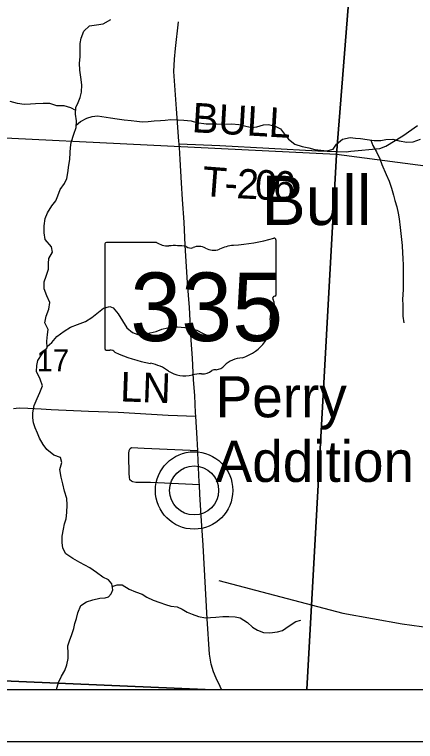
# Model space of a CAD drawing. Extents: x 0 to 40.8, y 0 to 22.
# Drawn here: x 3.599 to 4.37, y 14 to 15.397 of the extents above; entities that cross this region are included whole.
import ezdxf

# ---------------------------------------------------------------- set-up
doc = ezdxf.new("R2010")
doc.units = 0
for name, color, linetype in [('Default', 7, 'Continuous'), ('GM_X_County_Road', 7, 'Continuous'), ('GM_X_Minor_River', 7, 'Continuous'), ('GM_X_Minor_River_Text', 7, 'Continuous'), ('GM_X_Section', 7, 'Continuous'), ('GM_X_Section_Text', 7, 'Continuous'), ('GM_X_State_Location', 7, 'Continuous'), ('GM_X_State_Route', 7, 'Continuous'), ('GM_X_State_Shield', 7, 'Continuous'), ('GM_X_Township_Road', 7, 'Continuous'), ('GM_X_Township_Road_Text', 7, 'Continuous'), ('GM_X_Unincorporated', 7, 'Continuous'), ('GM_X_Unincorporated_Location', 7, 'Continuous'), ('GM_X_Unincorporated_Text', 7, 'Continuous'), ('SH_Cut_Line', 7, 'Continuous'), ('SH_Data', 7, 'Continuous')]:
    doc.layers.add(name, color=color, linetype=linetype)

msp = doc.modelspace()

# ---------------------------------------------------------------- linework, layer by layer
at = {"layer": 'Default'}
msp.add_lwpolyline([(2.1, 16.4387), (2.1, 14.1), (8.9, 14.1), (8.9, 16.9831), (7.7161, 17.0658), (7.7144, 17.066), (7.54, 17.0745), (7.4495, 17.0841), (6.9172, 17.1197), (6.1785, 17.166), (5.6278, 17.197), (5.3407, 17.2146), (4.8294, 17.2493), (4.5348, 17.2687), (3.4481, 17.3334), (3.1244, 17.3534), (2.8484, 17.3691), (2.8463, 17.3693), (2.4594, 17.3966), (2.4379, 17.0913), (2.3911, 16.4258)], close=True, dxfattribs=at)
at = {"layer": 'GM_X_County_Road'}
for points in [[(3.9661, 14.1), (4.1612, 14.1), (4.2184, 15.1287), (3.1769, 15.1799), (3.1139, 14.1362)], [(4.1612, 14.1), (5.1921, 14.1), (5.2555, 14.9926), (4.2184, 15.1287)], [(3.1117, 14.1), (3.9661, 14.1), (3.1139, 14.1362)]]:
    msp.add_lwpolyline(points, close=True, dxfattribs=at)
at = {"layer": 'GM_X_Minor_River'}
for points in [[(3.78, 14.311), (3.7691, 14.3156), (3.757, 14.3248), (3.7441, 14.3339), (3.7244, 14.3439), (3.7112, 14.3519), (3.6979, 14.3607), (3.6923, 14.3717), (3.6908, 14.3827), (3.6908, 14.3945), (3.6932, 14.4081), (3.6955, 14.4184), (3.6981, 14.4279), (3.6997, 14.4404), (3.7005, 14.4552), (3.6994, 14.4673), (3.6953, 14.4814), (3.6923, 14.4951), (3.6889, 14.5084), (3.6863, 14.5228), (3.6901, 14.5361), (3.6875, 14.5456), (3.6746, 14.5505), (3.6614, 14.5612), (3.6542, 14.5707), (3.647, 14.5833), (3.6433, 14.5928), (3.6391, 14.603), (3.6357, 14.6125), (3.6343, 14.6224), (3.6343, 14.6319), (3.6366, 14.6456), (3.6427, 14.6596), (3.6477, 14.671), (3.653, 14.6838), (3.6485, 14.6968), (3.6413, 14.7112), (3.6418, 14.7226), (3.6437, 14.7325), (3.6521, 14.7453), (3.662, 14.7567), (3.6612, 14.7696), (3.6628, 14.7821), (3.664, 14.792), (3.6576, 14.8049), (3.6602, 14.8178), (3.6648, 14.8311), (3.6668, 14.8436), (3.6611, 14.8569), (3.6559, 14.8702), (3.6563, 14.8835), (3.6597, 14.8945), (3.6643, 14.9077), (3.6643, 14.9187), (3.6651, 14.9282), (3.672, 14.9404), (3.6705, 14.951), (3.6577, 14.9651), (3.6562, 14.9776), (3.6558, 14.9916), (3.6578, 15.0057), (3.6627, 15.0163), (3.6711, 15.0296), (3.6787, 15.0394), (3.6826, 15.0489), (3.6871, 15.0614), (3.6955, 15.0724), (3.6997, 15.0826), (3.7017, 15.0932), (3.7036, 15.108), (3.7055, 15.1186), (3.7059, 15.1323), (3.7067, 15.1418), (3.7083, 15.1516), (3.7133, 15.1676), (3.7175, 15.1804), (3.7183, 15.193), (3.7164, 15.2059), (3.7172, 15.2188), (3.7214, 15.2282), (3.7252, 15.2381), (3.7279, 15.2483), (3.7287, 15.2624), (3.7265, 15.2768), (3.725, 15.2905), (3.7243, 15.3038), (3.7251, 15.3159), (3.7251, 15.3296), (3.7255, 15.3417), (3.7271, 15.3519), (3.7321, 15.3656), (3.7431, 15.3758), (3.7567, 15.3777), (3.7696, 15.3795), (3.7845, 15.3882)], [(3.7168, 15.213), (3.7077, 15.2184), (3.6945, 15.2219), (3.6804, 15.2223), (3.6668, 15.2262), (3.6539, 15.2262), (3.6395, 15.2259), (3.63, 15.2255), (3.6175, 15.2248), (3.6046, 15.2264), (3.5906, 15.2302)], [(3.7178, 15.1851), (3.7258, 15.1918), (3.7384, 15.1982), (3.7486, 15.2016), (3.7589, 15.2027), (3.7837, 15.1992)], [(3.7837, 15.1992), (3.7963, 15.1973), (3.8103, 15.1951), (3.8232, 15.1935), (3.8346, 15.1924), (3.8448, 15.1913), (3.8562, 15.192), (3.8679, 15.1932), (3.8796, 15.1939), (3.8891, 15.1943), (3.8997, 15.1958), (3.9137, 15.195), (3.9247, 15.1947), (3.9387, 15.1931), (3.9494, 15.1901), (3.9679, 15.1874), (3.9778, 15.1874), (3.988, 15.1871), (3.9997, 15.1867), (4.0168, 15.1871), (4.0308, 15.1863), (4.0437, 15.1829), (4.0554, 15.1802), (4.0653, 15.1817), (4.0782, 15.1855), (4.0876, 15.1859), (4.1005, 15.1829), (4.1107, 15.1776), (4.1183, 15.1677), (4.1259, 15.1582), (4.1384, 15.1483), (4.1524, 15.1438), (4.1649, 15.1411), (4.177, 15.1381), (4.1884, 15.1366), (4.1998, 15.1354), (4.2119, 15.1385), (4.2183, 15.1483), (4.2297, 15.1578), (4.2449, 15.1612), (4.2547, 15.1601), (4.2649, 15.1589), (4.2771, 15.1574), (4.2911, 15.1551), (4.3036, 15.1555), (4.3134, 15.157), (4.3271, 15.1578), (4.3392, 15.1548), (4.3536, 15.1521), (4.3657, 15.1529), (4.3801, 15.1578)], [(4.2843, 15.1562), (4.2884, 15.1457), (4.2956, 15.1335), (4.3017, 15.1199), (4.3059, 15.1089), (4.3142, 15.0899), (4.3195, 15.077), (4.324, 15.0637), (4.3278, 15.0504), (4.3305, 15.0398), (4.3343, 15.028), (4.3369, 15.0159), (4.3388, 15.0049), (4.3407, 14.9882), (4.3422, 14.9764), (4.3433, 14.9647), (4.3445, 14.9537), (4.3452, 14.9389), (4.346, 14.9294), (4.3464, 14.915), (4.3464, 14.8687), (4.3456, 14.8497), (4.346, 14.8395), (4.346, 14.8285), (4.3463, 14.8174), (4.3482, 14.8049)], [(3.6618, 14.7591), (3.6711, 14.7669), (3.6802, 14.7786), (3.6943, 14.7888), (3.7065, 14.7964), (3.7201, 14.8013), (3.7353, 14.8073), (3.7475, 14.8148), (3.7604, 14.8254), (3.7702, 14.8333), (3.7822, 14.8361)], [(3.7822, 14.8361), (3.7887, 14.8338), (3.7985, 14.8221), (3.8065, 14.8088), (3.8152, 14.7955), (3.8262, 14.7864), (3.8364, 14.7826), (3.8496, 14.7826), (3.8603, 14.7856), (3.8716, 14.7883), (3.8826, 14.7925), (3.8932, 14.7951), (3.9031, 14.7974), (3.9125, 14.7974), (3.9269, 14.7959), (3.9375, 14.7936), (3.9497, 14.7906), (3.9607, 14.7849), (3.9701, 14.7807), (3.9838, 14.7799), (3.9932, 14.7807)], [(3.7799, 14.2783), (3.7851, 14.2841), (3.7882, 14.2912), (3.7862, 14.3028), (3.78, 14.311)], [(3.787, 14.2981), (3.7963, 14.3009), (3.806, 14.3011), (3.8193, 14.2931), (3.8318, 14.2874), (3.8443, 14.2833), (3.8537, 14.2776), (3.8655, 14.2719), (3.8787, 14.2669), (3.8894, 14.2631), (3.9, 14.2601), (3.9121, 14.2586), (3.9216, 14.2544), (3.931, 14.2487), (3.9405, 14.2449), (3.953, 14.2404), (3.9663, 14.2377), (3.9761, 14.2381), (3.9863, 14.2388), (3.9996, 14.24), (4.011, 14.2404), (4.0235, 14.2396), (4.0333, 14.2377), (4.0473, 14.2286), (4.0568, 14.2199), (4.0667, 14.2138), (4.078, 14.2096), (4.0901, 14.2089), (4.1049, 14.2108), (4.1144, 14.2134), (4.1273, 14.2225), (4.1405, 14.2309), (4.15, 14.2331)], [(3.6796, 14.1), (3.6836, 14.1136), (3.6893, 14.1258), (3.6958, 14.1367), (3.7, 14.147), (3.7023, 14.1595), (3.7023, 14.169), (3.7016, 14.1838), (3.7047, 14.1933), (3.7092, 14.2054), (3.7131, 14.2172), (3.7154, 14.2266), (3.7181, 14.2365), (3.7207, 14.2475), (3.7269, 14.2611), (3.7375, 14.2683), (3.75, 14.2724), (3.7629, 14.2754), (3.7733, 14.2762), (3.7799, 14.2783)]]:
    msp.add_lwpolyline(points, dxfattribs=at)
at = {"layer": 'GM_X_Section'}
msp.add_lwpolyline([(3.9129, 16.1794), (4.2989, 16.1489), (4.2184, 15.1287), (3.1769, 15.1799), (3.1915, 15.3835)], dxfattribs=at)
msp.add_lwpolyline([(5.3264, 16.0026), (5.2555, 14.9926), (4.2184, 15.1287), (4.2989, 16.1489)], close=True, dxfattribs=at)
at = {"layer": 'GM_X_State_Route'}
msp.add_lwpolyline([(3.9973, 14.1), (3.9945, 14.1055), (3.9867, 14.1214), (3.9817, 14.1337), (3.9772, 14.1484), (3.9743, 14.1681), (3.9699, 14.2358), (3.962, 14.3771), (3.9589, 14.4244), (3.9554, 14.4745), (3.9547, 14.4936), (3.9545, 14.4985), (3.9517, 14.5548), (3.9514, 14.5595), (3.9502, 14.5825), (3.9477, 14.6256), (3.9472, 14.6321), (3.9456, 14.6652), (3.9434, 14.6951), (3.9412, 14.7369), (3.9386, 14.7717), (3.9354, 14.834), (3.9321, 14.8815), (3.9275, 14.9539), (3.9251, 14.9984), (3.922, 15.042), (3.92, 15.074), (3.9174, 15.1188), (3.9162, 15.1418), (3.9155, 15.1489), (3.915, 15.1542), (3.9104, 15.2159), (3.9056, 15.2878), (3.9066, 15.3118), (3.9087, 15.3321), (3.9145, 15.3832)], dxfattribs=at)
at = {"layer": 'GM_X_State_Shield'}
for p, q in [((3.7725, 14.9557), (3.7725, 14.7556)), ((3.8723, 14.9591), (3.7757, 14.9591)), ((4.1021, 14.8594), (4.1021, 14.9641)), ((4.102, 14.8594), (4.1021, 14.8594))]:
    msp.add_line(p, q, dxfattribs=at)
for centre, major_axis, start_param, end_param in [((3.9847, 15.232), (0.3495, 0), 4.814394, 5.042369), ((4.0984, 14.9645), (0.00367, 0), 6.141152, 7.989035), ((3.7763, 14.9561), (0.00382, 0), 1.712693, 3.28349), ((3.8952, 14.9824), (0.037, 0), 4.042523, 4.731795), ((3.9075, 14.8468), (0.133, 0), 1.404758, 1.657858), ((4.0292, 14.898), (0.0703, 0), 1.699011, 2.107814), ((3.9377, 14.9571), (0.0107, 0), 3.836095, 5.185415), ((3.9534, 14.934), (0.0222, 0), 0.950623, 2.079405), ((3.9821, 14.9657), (0.0267, 0), 4.081561, 5.145723), ((4.1012, 14.8517), (0.00568, 0), 1.883978, 3.671073), ((4.0982, 14.859), (0.00393, 0), 5.05454, 6.418171), ((4.0651, 14.8385), (0.0341, 0), 5.934695, 6.695948), ((4.1152, 14.8156), (0.0248, 0), 2.387724, 3.262537), ((4.0042, 14.8023), (0.0874, 0), 5.101752, 6.440018), ((3.7763, 14.7551), (0.00385, 0), 3.00124, 4.508301), ((3.7769, 14.7756), (0.0294, 0), 4.665946, 4.897461), ((3.7829, 14.744), (0.0106, 0), 0.519207, 1.627899), ((3.9167, 14.9238), (0.2524, 0), 4.195997, 4.488961), ((4.0411, 14.6994), (0.0479, 0), 1.647645, 2.488434), ((3.8415, 14.6657), (0.079, 0), 0.823519, 1.323587), ((3.9804, 14.7362), (0.0282, 0), 4.937069, 5.64225), ((3.9269, 14.743), (0.0501, 0), 4.026481, 4.996735), ((3.9558, 14.6738), (0.0412, 0), 1.495662, 1.94098), ((3.9595, 14.728), (0.0267, 0), 4.691044, 5.507374), ((3.9836, 14.7087), (0.00752, 0), 1.147584, 2.315152)]:
    msp.add_ellipse(centre, major_axis=major_axis, ratio=0.8, start_param=start_param, end_param=end_param, dxfattribs=at)
at = {"layer": 'GM_X_Township_Road'}
for points in [[(3.9155, 15.1489), (3.9943, 15.1458), (4.1827, 15.1354), (4.2368, 15.1338), (4.2462, 15.1347), (4.3017, 15.1399), (4.3136, 15.1446), (4.3462, 15.1646), (4.3743, 15.1842)], [(3.5969, 14.6403), (3.6023, 14.6408), (3.6094, 14.6413), (3.6249, 14.6406), (3.6506, 14.6394)], [(3.6506, 14.6394), (3.6694, 14.6385), (3.7414, 14.635), (3.7982, 14.6328), (3.8945, 14.6274), (3.9477, 14.6256)], [(3.8266, 14.4992), (3.8238, 14.5004), (3.821, 14.503), (3.8202, 14.5078), (3.8197, 14.5154), (3.8195, 14.5205), (3.8189, 14.5439), (3.8189, 14.5533), (3.8195, 14.5594), (3.8217, 14.5635), (3.8243, 14.5653)], [(3.8243, 14.5653), (3.8484, 14.5638), (3.9514, 14.5595)], [(3.9547, 14.4936), (3.8607, 14.4979), (3.8322, 14.4979), (3.8266, 14.4992)], [(3.9919, 14.3096), (4.2309, 14.2467), (4.3445, 14.2259), (4.475, 14.2079), (4.5064, 14.2128), (4.5493, 14.2793), (4.5603, 14.3214), (4.5615, 14.3282)]]:
    msp.add_lwpolyline(points, dxfattribs=at)
at = {"layer": 'GM_X_Unincorporated'}
for radius in [0.0744, 0.0472]:
    msp.add_circle((3.9445, 14.4826), radius, dxfattribs=at)
at = {"layer": 'GM_X_Unincorporated_Location'}
msp.add_line((3.9445, 14.4826), (3.9445, 14.4826), dxfattribs=at)
at = {"layer": 'SH_Cut_Line'}
msp.add_lwpolyline([(2.1, 17.4153), (2.1, 14.1), (8.9, 14.1), (8.9, 16.9831), (7.7161, 17.0658), (7.7144, 17.066), (7.54, 17.0745), (7.4495, 17.0841), (6.9172, 17.1197), (6.1785, 17.166), (5.6278, 17.197), (5.3407, 17.2146), (4.8294, 17.2493), (4.5348, 17.2687), (3.4481, 17.3334), (3.1244, 17.3534), (2.8484, 17.3691), (2.8463, 17.3693), (2.4594, 17.3966)], close=True, dxfattribs=at)
at = {"layer": 'SH_Data'}
for p, q in [((2.1, 14.1), (8.9, 14.1)), ((2, 14), (9, 14))]:
    msp.add_line(p, q, dxfattribs=at)

# ---------------------------------------------------------------- texts
at = {"layer": 'GM_X_Minor_River_Text'}
msp.add_text('Bull', height=0.0947, rotation=359.9973, dxfattribs=at).set_placement((4.0746, 14.9929))
at = {"layer": 'GM_X_Section_Text'}
msp.add_text('17', height=0.04186, rotation=0, dxfattribs=at).set_placement((3.6417, 14.7118))
at = {"layer": 'GM_X_State_Location'}
for s in ['s', 'r']:
    msp.add_text(s, height=0.000189, dxfattribs=at).set_placement((3.9336, 14.8423))
msp.add_text('335', height=0.000189, rotation=0, dxfattribs=at).set_placement((3.8667, 14.8285))
at = {"layer": 'GM_X_State_Shield'}
msp.add_text('335', height=0.13184, dxfattribs=at).set_placement((3.8216, 14.7697))
at = {"layer": 'GM_X_Township_Road_Text'}
for s, height, rotation, p in [('BULL', 0.05682, 356.6348, (3.9394, 15.1714)), ('T', 0.0568, 355.6802, (3.9584, 15.0492)), ('2', 0.0568, 356.8975, (4.0253, 15.0446)), ('0', 0.0568, 357.0027, (4.0604, 15.0427)), ('6', 0.0568, 357.0208, (4.0954, 15.0409)), ('-', 0.0568, 356.6742, (4.0018, 15.046)), ('LN', 0.05682, 357.9353, (3.8017, 14.6539))]:
    msp.add_text(s, height=height, rotation=rotation, dxfattribs=at).set_placement(p)
at = {"layer": 'GM_X_Unincorporated_Text'}
for s, p in [('Perry', (3.9859, 14.6232)), ('Addition', (3.9859, 14.499))]:
    msp.add_text(s, height=0.07898, rotation=0, dxfattribs=at).set_placement(p)

doc.saveas('drawing.dxf')
